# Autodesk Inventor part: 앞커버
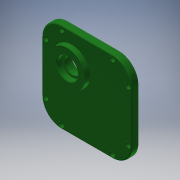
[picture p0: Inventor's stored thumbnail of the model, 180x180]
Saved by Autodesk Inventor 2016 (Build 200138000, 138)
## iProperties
Created: 2016-12
Part Number: 앞커버
Material: 알루미늄 6061
Document SubType Name: Modeling
Designer: mduedu
Density: 2.71 g/cm^3
Appearance: 매끄러움 - 짙은 산림 녹색
Mass: 518.945 g
Surface Area: 476.271 cm^2
Volume: 191.493 cm^3
Author: mduedu
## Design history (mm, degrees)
sketch "스케치1"
  geometry: L1 (-46, 42)-(-46, -36); L2 (-16, 72)-(62, 72); L3 (92, 42)-(92, -36); L4 (62, -66)-(-16, -66); A1 r 30 centre (-16, -36) between (-46, -36) and (-16, -66); A2 r 30 centre (62, 42) between (92, 42) and (62, 72); A3 r 30 centre (62, -36) between (62, -66) and (92, -36); A4 r 30 centre (-16, 42) between (-16, 72) and (-46, 42); 1 further point
  constraints: 8 end point, 8 point on circle, 8 tangent, 4 centre point, 3 equal radius, 2 perpendicular, 1 horizontal
  dimensions: "d89" = 30 radius of A2; "d90" = 92 distance from line of L3 point (0, 0); "d91" = 138 distance between parallel lines of L4 L2; "d92" = 72 distance from line of point (0, 0) L2; "d114" = 46 distance from line of point (0, 0) L1
extrude "돌출1" new body sketch "스케치1" distance "d3" = 10; taper "d4" = 0 deg
sketch "스케치2"
  geometry: C1 r 21 at (0, 26); 1 further point
  constraints: 1 centre point, 1 vertical alignment
  dimensions: "d5" = 42 diameter of C1; "d7" = 26 distance of C1.centre point (0, 0)
extrude "돌출2" join sketch "스케치2" distance "d8" = 7; taper "d9" = 0 deg
sketch "스케치3"
  geometry: C1 r 15 at (0, -28.87); C2 r 21 at (0, 26) reference; C3 r 15 at (-54.87, 26); 1 further point
  constraints: 2 centre point, 1 horizontal alignment, 1 vertical alignment
  dimensions: "d10" = 30 diameter of C1; "d71" = 54.87 distance of C1.centre C2.centre; "d94" = 30 diameter of C3; "d95" = 54.87 distance of C2.centre C3.centre
extrude "돌출3" join sketch "스케치3" distance "d12" = 7; taper "d13" = 0 deg; dims "d50" = 90 deg
sketch "스케치4"
  geometry: C1 r 21 at (0, 26) reference; C2 r 28 at (0, 26); 1 further point
  constraints: 1 centre point, 1 coincident
  dimensions: "d14" = 56 diameter of C2
extrude "돌출4" join sketch "스케치4" distance "d15" = 7; taper "d16" = -5 deg
hole "구멍1" diameter "d19" = 35; stored, may be unused: countersink angle "d23" = 90 deg, drill point angle "d25" = 0 deg; dims "d17" = 10, "d18" = 10, "d20" = 6, "d21" = 4, "d22" = 2, "d24" = 10
hole "구멍2" diameter "d28" = 22; stored, may be unused: countersink angle "d32" = 90 deg, drill point angle "d34" = 0 deg; dims "d26" = 10, "d27" = 10, "d29" = 6, "d30" = 4, "d31" = 2, "d33" = 7
hole "구멍8" diameter "d98" = 22; stored, may be unused: countersink angle "d102" = 90 deg, drill point angle "d104" = 0 deg; dims "d96" = 10, "d97" = 10, "d99" = 6, "d100" = 4, "d101" = 2, "d103" = 7
hole "구멍3" diameter "d37" = 19; stored, may be unused: countersink angle "d41" = 90 deg, drill point angle "d43" = 0 deg; dims "d35" = 10, "d36" = 10, "d38" = 6, "d39" = 4, "d40" = 2, "d42" = 1
hole "구멍9" diameter "d107" = 19; stored, may be unused: countersink angle "d111" = 90 deg, drill point angle "d113" = 0 deg; dims "d105" = 10, "d106" = 10, "d108" = 6, "d109" = 4, "d110" = 2, "d112" = 1
hole "구멍4" diameter "d46" = 32; stored, may be unused: countersink angle "d50" = 90 deg, drill point angle "d52" = 0 deg; dims "d44" = 10, "d45" = 10, "d47" = 6, "d48" = 4, "d49" = 2, "d51" = 8
hole "구멍5" diameter "d55" = 25; stored, may be unused: countersink angle "d59" = 90 deg, drill point angle "d61" = 0 deg; dims "d53" = 10, "d54" = 10, "d56" = 6, "d57" = 4, "d58" = 2, "d60" = 8
fillet "모깎기1" dims "d62" = 0.3
fillet "모깎기2" dims "d63" = 2
chamfer "모따기1" distance "d64" = 1; stored, may be unused: second distance "d65" = 2, angle "d66" = 45 deg
fillet "모깎기4" dims "d68" = 2
fillet "모깎기5" dims "d69" = 0.3
fillet "모깎기6" dims "d70" = 2
sketch "스케치5"
  geometry: L1 (62, 72)-(-16, 72) reference; L2 (92, -36)-(92, 42) reference; L3 (-16, -66)-(62, -66) reference; L4 (-46, 42)-(-46, -36) reference; L5 (-40, 42)-(-40, -36); L6 (-16, -60)-(62, -60); L7 (86, -36)-(86, 42); L8 (62, 66)-(-16, 66); A1 r 30 centre (62, 42) between (92, 42) and (62, 72) reference; A2 r 30 centre (62, -36) between (62, -66) and (92, -36) reference; A3 r 30 centre (-16, -36) between (-46, -36) and (-16, -66) reference; A4 r 30 centre (-16, 42) between (-16, 72) and (-46, 42) reference; A5 r 24 centre (-16, -36) between (-40, -36) and (-16, -60); A6 r 24 centre (62, -36) between (62, -60) and (86, -36); A7 r 24 centre (62, 42) between (86, 42) and (62, 66); A8 r 24 centre (-16, 42) between (-16, 66) and (-40, 42)
  constraints: 8 end point, 8 point on circle, 4 centre point, 7 other
  dimensions: "d93" = 6 distance between parallel lines of L5 L4
sketch "스케치7"
  geometry: L1 (62, 66)-(-16, 66) reference; L2 (86, -36)-(86, 42) reference; L3 (-16, -60)-(62, -60) reference; L4 (-40, 42)-(-40, -36) reference; A1 r 24 centre (62, 42) between (86, 42) and (62, 66) reference; A2 r 24 centre (62, -36) between (62, -60) and (86, -36) reference; A3 r 24 centre (-16, -36) between (-40, -36) and (-16, -60) reference; A4 r 24 centre (-16, 42) between (-16, 66) and (-40, 42) reference; 8 further points
  constraints: 8 coincident
hole "구멍7" sketch "스케치7" at (-40, 42), (-40, -36), (-16, -60), (62, -60), (86, -36), (86, 42), (62, 66), (-16, 66) diameter "d80" = 4.5; stored, may be unused: countersink angle "d84" = 90 deg, drill point angle "d86" = 0 deg; dims "d81" = 6, "d82" = 8, "d83" = 4.6, "d85" = 8
node "솔리드1"
